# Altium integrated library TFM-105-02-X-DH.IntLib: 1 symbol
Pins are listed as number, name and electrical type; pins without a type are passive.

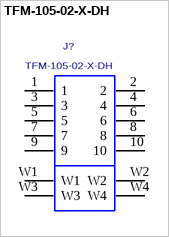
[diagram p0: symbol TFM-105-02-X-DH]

## TFM-105-02-X-DH
designator J?
0.050" Terminal  Strip, Surface Mount, Double Row Horizontal Mount..; MANUFACTURER: SAMTEC
footprint TFM-105-02-X-DH
pins: 1, 2, 3, 4, 5, 6, 7, 8, 9, 10, W1, W2, W3, W4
